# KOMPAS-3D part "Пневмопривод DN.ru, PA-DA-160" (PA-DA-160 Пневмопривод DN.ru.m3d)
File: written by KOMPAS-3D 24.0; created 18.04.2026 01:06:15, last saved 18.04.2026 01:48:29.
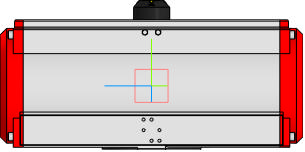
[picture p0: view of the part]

Document properties: Автор: DN.ru; Полное имя файла: C:\Работа\PA-DA-х Пневмопривод DN.ru\160\PA-DA-160 Пневмопривод DN.ru.m3d

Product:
- Part/product: Пневмопривод DN.ru  | designation PA-DA-160
    Масса: 20
    Раздел спецификации: Прочие изделия
    Примечание: D290-00299

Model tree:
1. Операция без истории:1

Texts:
  PA-DA-160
